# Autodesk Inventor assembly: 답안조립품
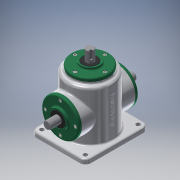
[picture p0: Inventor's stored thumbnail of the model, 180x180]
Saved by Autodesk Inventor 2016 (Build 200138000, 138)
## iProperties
Created: 2021-02
Part Number: 답안조립품
Material: 일반
Document SubType Name: Assembly
Designer: user
Author: user
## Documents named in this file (16)
- C:\Users\user\Desktop\710206V1003\답안조립품.iam
- C:\Users\user\Desktop\710206V1003\메인 베벨기어.ipt
- C:\Users\user\Desktop\710206V1003\메인 축.ipt
- 메인 축.ipt
- C:\Users\user\Desktop\710206V1003\베어링 6203.ipt
- C:\Users\user\Desktop\710206V1003\본체.ipt
- C:\Users\user\Desktop\710206V1003\볼트 M4.ipt
- 볼트 M4.ipt
- C:\Users\user\Desktop\710206V1003\서브 베벨기어.ipt
- C:\Users\user\Desktop\710206V1003\서브 축.ipt
- 서브 축.ipt
- C:\Users\user\Desktop\710206V1003\오일 실.ipt
- 오일 실.ipt
- C:\Users\user\Desktop\710206V1003\커버.ipt
- C:\Users\user\Desktop\710206V1003\키 4x4.ipt
- C:\Users\user\Desktop\710206V1003\키 5x5.ipt
